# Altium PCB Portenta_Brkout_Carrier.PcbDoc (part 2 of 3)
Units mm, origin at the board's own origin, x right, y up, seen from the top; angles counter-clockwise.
Board outline 163.96 x 72.14 mm, 4 copper layers (Top, GND, PWR, Bottom), stack 1.612 mm thick; 71 components, 171 nets, 700 pads, 387 vias.
Unrouted connection lines stored in the file: 2.
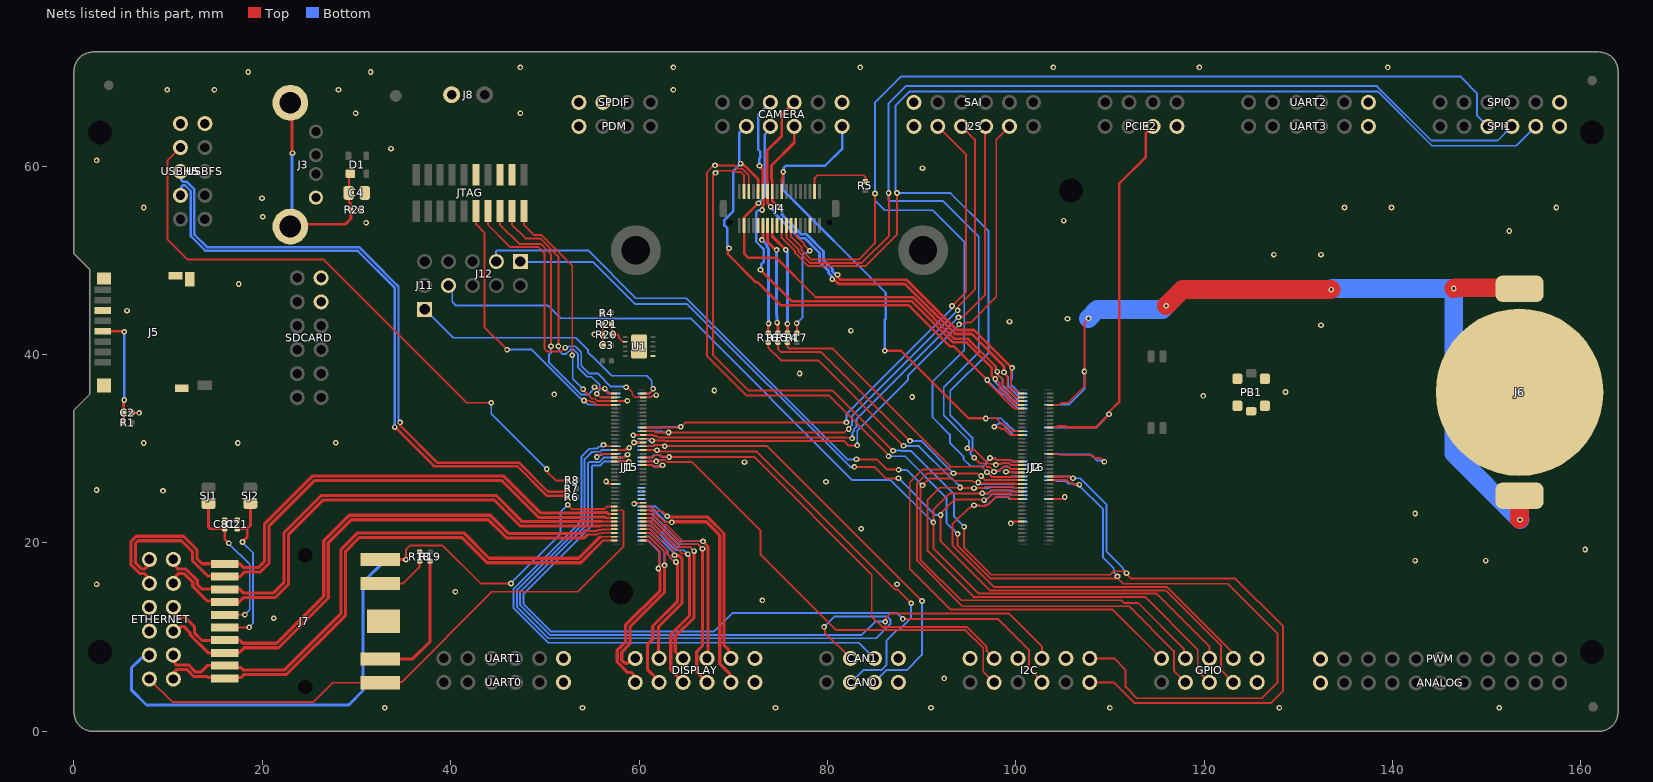
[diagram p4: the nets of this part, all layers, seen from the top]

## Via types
v1: diameter 0.6, hole 0.3, Top to Bottom, tented both sides, 387 vias

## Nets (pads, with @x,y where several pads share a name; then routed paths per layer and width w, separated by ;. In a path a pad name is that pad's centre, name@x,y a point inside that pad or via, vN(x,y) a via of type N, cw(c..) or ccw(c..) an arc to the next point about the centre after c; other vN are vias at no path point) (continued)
CAM.D1_1_P: CAMERA.10 J2.10 J4.28 J16.10 | length 62
  Top w0.2: v1(96.977,37.303) 97.053,37.227 97.053,37.051 99.695,34.41 99.754,34.41 99.9,34.264 J2.10@100.57,34.264
  Top w0.264: v1@69.537,51.287 69.473,51.222 69.473,50.997 69.44,50.964 69.44,50.652 72.423,47.669 72.627,47.669 75.032,45.264 88.607,45.264 92.976,40.895 93.385,40.895 v1(96.977,37.303) ; v1(70.79,60.274) 70.881,60.274 71.057,60.098 71.182,60.098 72.65,58.63 J4.28@72.65,57.324
  Bottom w0.2: v1(96.977,37.303) 98.532,35.748 98.71,35.748 99.824,34.634 99.879,34.634 100.244,34.269 100.825,34.269 J16.10@100.83,34.264
  Bottom w0.264: v1@69.537,51.287 69.537,51.378 69.369,51.545 69.369,53.433 69.034,53.768 69.034,54.252 70.025,55.243 70.025,59.508 70.68,60.163 v1(70.79,60.274) ; v1@70.667,60.177 70.637,60.207 70.637,63.53 71.347,64.24 CAMERA.10@71.4,64.24
  other v1: 69.551,51.293
CAM.D2_1_N: CAMERA.7 J2.8 J4.26 J16.8 | length 58.5
  Top w0.2: v1(97.819,37.407) 98.287,36.94 98.287,36.28 99.83,34.737 99.889,34.737 99.962,34.664 J2.8@100.57,34.664
  Top w0.264: v1(72.791,60.05) 72.791,59.959 73.15,59.6 J4.26@73.15,57.324 73.168,57.306 73.168,56.391 73.25,56.309 73.25,55.846 73.134,55.73 73.134,55.415 v1(73.07,55.351) ; v1(72.9,49) 76.245,45.655 88.968,45.655 93.337,41.286 94.783,41.286 97.472,38.597 97.472,37.73 97.795,37.407 v1(97.819,37.407)
  Bottom w0.2: v1(97.819,37.407) 97.896,37.331 97.896,37.024 99.959,34.961 100.014,34.961 100.306,34.669 100.825,34.669 J16.8@100.83,34.664
  Bottom w0.264: v1(72.791,60.05) 72.791,60.794 72.875,60.878 72.875,61.54 72.669,61.746 72.669,65.509 CAMERA.7@73.94,66.78 ; v1(72.9,49) 72.964,49.064 72.964,49.559 73.234,49.828 73.234,51.202 72.45,51.986 72.45,55.11 72.652,55.312 73.032,55.312 v1(73.07,55.351)
CAM.D2_1_P: CAMERA.8 J2.6 J4.33 J16.6 | length 56
  Top w0.2: v1@98.007,38.111 98.108,38.01 98.108,37.864 98.614,37.358 98.614,36.416 99.966,35.064 J2.6@100.57,35.064
  Top w0.264: v1(72.691,56.078) 71.168,54.554 71.168,53.742 J4.33@71.15,53.724 71.15,50.75 71.634,50.266 74.593,50.266 78.766,46.093 89.074,46.093 89.12,46.047 89.13,46.047 93.499,41.677 94.945,41.677 97.863,38.759 97.863,38.454 98.031,38.286 v1(98.031,38.195)
  Bottom w0.2: v1(98.031,38.195) 98.108,38.118 98.108,37.864 98.614,37.358 98.614,36.768 100.095,35.288 100.15,35.288 100.369,35.069 100.825,35.069 J16.6@100.83,35.064
  Bottom w0.264: v1(72.691,56.078) 73.35,56.737 73.35,63.37 73.94,63.96 CAMERA.8@73.94,64.24
CAM.D3_1_N: CAMERA.5 J2.4 J4.24 J16.4 | length 53.4
  Top w0.2: v1(98.755,38.125) 98.755,38.035 99.104,37.685 99.104,36.388 100.028,35.464 J2.4@100.57,35.464
  Top w0.3: v1(73.973,55.701) 73.973,55.782 73.659,56.096 73.659,56.479 73.65,56.488 J4.24@73.65,57.324 73.65,58.372 73.595,58.427 73.595,61.66 75.162,63.227 75.162,65.462 CAMERA.5@76.48,66.78 ; v1(80.525,48) 80.705,48 81.209,47.496 88.259,47.496 93.58,42.175 95.343,42.175 98.761,38.757 98.761,38.447 98.757,38.444 98.757,38.127 v1(98.755,38.125)
  Bottom w0.2: v1(98.755,38.125) 98.755,38.019 99.197,37.577 99.197,36.648 100.23,35.615 100.285,35.615 100.431,35.469 100.825,35.469 J16.4@100.83,35.464
  Bottom w0.3: v1(73.973,55.701) 73.973,55.623 74.465,55.132 74.465,54.94 77.057,52.348 77.608,52.348 79.169,50.788 79.169,49.842 80.115,48.897 80.115,48.673 80.468,48.32 80.468,48.057 v1(80.525,48)
CAM.D3_1_P: CAMERA.6 J2.2 J4.22 J16.2 | length 49.6
  Top w0.2: v1(99.619,38.59) 99.619,38.482 99.486,38.349 99.486,37.32 99.481,37.314 99.481,36.474 99.786,36.169 100.015,36.169 100.32,35.864 J2.2@100.57,35.864
  Top w0.264: J4.22@74.15,57.324 74.168,57.306 74.168,56.306 v1(74.797,55.677)
  Top w0.3: J4.22@74.15,57.324 74.15,58.548 74.073,58.625 74.073,60.094 76.48,62.501 CAMERA.6@76.48,64.24 ; v1(81.073,48.478) 81.073,48.269 81.396,47.946 88.413,47.946 93.731,42.628 95.581,42.628 v1(99.619,38.59)
  Bottom w0.2: v1(99.619,38.59) 99.619,37.422 99.524,37.327 99.524,36.783 100.365,35.942 100.457,35.942 J16.2@100.53,35.869
  Bottom w0.3: v1(74.797,55.677) 74.797,55.596 75.167,55.226 75.167,54.842 77.234,52.775 77.785,52.775 79.596,50.964 79.596,50.019 80.542,49.074 80.542,48.849 80.763,48.628 80.842,48.628 80.992,48.478 v1(81.073,48.478)
CAM.HS_1: CAMERA.2 J2.22 J4.18 J16.22 | length 58.2
  Top w0.2: v1(96.823,33.222) 96.847,33.246 97.938,33.246 98.736,32.448 98.941,32.448 99.525,31.864 J2.22@100.57,31.864
  Top w0.264: J4.18@75.15,57.324 75.15,58.541 75.241,58.632 75.241,59.355 v1@75.3,59.414 ; v1(86.099,40.411) 87.825,40.411 95.014,33.222 v1(96.823,33.222)
  Bottom w0.2: v1(96.823,33.222) 96.847,33.246 98.437,33.246 99.011,32.672 99.066,32.672 99.874,31.864 J16.22@100.83,31.864
  Bottom w0.264: CAMERA.2@81.56,64.24 81.56,61.849 79.775,60.064 75.613,60.064 75.36,59.811 75.36,59.474 75.3,59.414 75.3,57.464 86.2,46.564 86.2,43.827 86.099,43.726 v1(86.099,40.411)
  other v1: 75.314,59.421
CAN0.RX_1: CAN0.3 J1.52 J15.52 | length 51
  Top w0.2: J1.52@60.47,30.264 61.551,30.264 61.689,30.402 62.491,30.402 62.541,30.352 v1@62.687,30.352 ; v1(62.726,30.275) 73.611,30.275 v1(90.043,13.843)
  Bottom w0.19: J15.52@60.23,30.264 61.558,30.264 61.691,30.397 62.493,30.397 62.615,30.275 v1(62.726,30.275)
  Bottom w0.2: CAN0.3@85,5.2 86.328,6.528 88.465,6.528 90.043,8.106 v1(90.043,13.843)
CAN0.TX_1: CAN0.2 J1.50 J15.50 | length 49.5
  Top w0.2: J1.50@60.47,29.864 61.654,29.864 61.809,29.709 61.917,29.709 v1(61.917,29.852) ; v1@61.974,29.709 72.526,29.709 79.849,22.386 87.173,15.062 87.427,15.062 v1(88.9,13.589)
  Bottom w0.19: J15.50@59.99,29.864 61.905,29.864 v1(61.917,29.852)
  Bottom w0.2: CAN0.2@82.46,5.2 82.511,5.2 83.808,6.497 85.733,6.497 86.263,7.027 86.263,9.628 87.418,10.783 87.634,10.783 88.9,12.049 v1(88.9,13.589)
CAN1.RX_1: CAN1.3 J1.51 J15.51 | length 65.2
  Top w0.19: v1(56.222,30.409) 56.3,30.33 56.525,30.33 56.593,30.262 56.595,30.264 J1.51@57.39,30.264
  Bottom w0.19: v1(56.222,30.409) 56.3,30.33 56.59,30.33 56.657,30.264 J15.51@57.65,30.264
  Bottom w0.2: v1(56.222,30.409) 56.113,30.409 55.913,30.209 55.739,30.209 55.554,30.024 55.157,30.024 55.135,30.002 54.705,30.002 53.88,29.177 53.88,22.325 46.677,15.122 46.677,13.091 50.37,9.398 83.342,9.398 CAN1.3@85,7.74
CAN1.TX_1: CAN1.2 J1.49 J15.49 | length 79.8
  Top w0.19: J1.49@57.39,29.864 58.463,29.864 58.527,29.928 58.662,29.928 58.849,30.115 v1(58.96,30.115)
  Top w0.2: v1(79.659,11.091) 79.736,11.014 79.736,10.464 CAN1.2@82.46,7.74
  Bottom w0.19: 54.975,29.646 54.986,29.657 55.277,29.657 55.299,29.679 55.811,29.679 55.996,29.864 J15.49@57.65,29.864 58.484,29.864 58.536,29.916 58.592,29.916 58.614,29.938 58.672,29.938 58.849,30.115 v1(58.96,30.115)
  Bottom w0.2: 54.975,29.646 54.23,28.901 54.23,22.18 47.027,14.977 47.027,13.236 50.379,9.884 85.171,9.884 86.701,11.414 86.701,11.87 86.379,12.192 80.76,12.192 v1(79.659,11.091)
CIPO_OMV_1: J2.40 J4.15 J16.40 SPI1.4 | length 145.5
  Top w0.2: J4.15@75.65,53.724 75.65,52.439 76.917,51.172 76.917,50.951 78.128,49.739 83.664,49.739 86.55,52.625 86.55,57.108 v1(86.5,57.159) ; v1(94.848,30.059) 94.956,30.059 95.147,29.868 95.655,29.868 97.108,28.415 97.405,28.415 97.454,28.366 97.82,28.366 v1(97.897,28.289) 97.974,28.366 98.489,28.366 98.587,28.464 99.308,28.464 99.348,28.424 99.374,28.424 99.534,28.264 J2.40@100.57,28.264
  Bottom w0.2: v1(94.848,30.059) 94.848,30.167 95.039,30.358 95.039,30.874 92.355,33.558 92.355,36.515 96.076,40.236 96.076,52.507 92.283,56.3 86.617,56.3 86.5,56.417 v1(86.5,57.159) 86.5,66.684 88.33,68.514 138.352,68.514 144.133,62.733 151.173,62.733 SPI1.4@152.68,64.24 ; v1(97.897,28.289) 97.974,28.366 98.443,28.366 98.541,28.464 99.333,28.464 99.533,28.264 J16.40@100.83,28.264
CK_OMV_1: J2.38 J4.13 J16.38 SPI1.3 | length 145
  Top w0.2: J4.13@76.15,53.724 76.15,52.496 77.267,51.379 77.267,51.096 78.273,50.089 83.307,50.089 85.05,51.832 v1(85.05,57.108) ; v1(97.274,29.027) 97.341,28.959 97.874,28.959 98.004,28.829 98.193,28.829 98.206,28.816 99.451,28.816 99.493,28.774 99.519,28.774 99.629,28.664 J2.38@100.57,28.664
  Bottom w0.2: v1(97.274,29.027) 97.268,29.027 96.914,28.673 96.914,28.477 96.579,28.142 95.216,28.142 94.445,28.914 94.445,29.19 93.016,30.618 93.016,31.497 91.163,33.35 91.163,37.094 94.539,40.47 94.539,51.969 91.183,55.325 86.09,55.325 85.05,56.365 v1(85.05,57.108) 85.05,66.729 87.86,69.539 147.177,69.539 148.999,67.717 148.999,65.381 SPI1.3@150.14,64.24 ; v1@97.329,29.082 97.457,28.954 97.874,28.954 97.994,28.834 98.188,28.834 98.208,28.814 99.478,28.814 99.628,28.664 J16.38@100.53,28.664
COPI_OMV_1: J2.42 J4.17 J16.42 SPI1.5 | length 149.4
  Top w0.2: J4.17@75.15,53.724 75.15,52.414 76.567,50.997 76.567,50.806 77.984,49.389 84.021,49.389 87.399,52.767 v1(87.399,57.159) ; v1(95.589,29.042) 96.192,28.439 96.589,28.439 96.963,28.065 97.26,28.065 97.7,27.624 v1(97.7,27.566) ; v1@97.711,27.614 97.787,27.69 98.308,27.69 98.732,28.114 99.163,28.114 99.203,28.074 99.229,28.074 99.439,27.864 J2.42@100.57,27.864
  Bottom w0.2: v1(95.589,29.042) 95.207,29.424 95.207,29.64 95.398,29.831 95.398,31.194 93.053,33.539 93.053,36.136 97.126,40.209 97.126,53.103 93.07,57.159 v1(87.399,57.159) 87.399,57.177 87.25,57.326 87.25,66.464 88.725,67.939 138.432,67.939 144.201,62.17 153.15,62.17 SPI1.5@155.22,64.24 ; v1(97.7,27.566) 97.777,27.642 98.26,27.642 98.582,27.964 98.732,28.114 99.188,28.114 99.338,27.964 99.438,27.864 J16.42@100.53,27.864
CS_OMV_1: J4.11 R17.1 | length 12.9
  Top w0.2: J4.11@76.65,53.724 76.65,52.624 77.523,51.752 77.523,51.618 v1(78.12,51.02) ; v1@76.725,43.314 76.773,43.266 R17.1@76.773,42.264
  Bottom w0.2: v1@76.725,43.314 77.375,43.964 77.375,50.614 77.516,50.756 77.747,50.756 78.012,51.02 v1(78.12,51.02)
  other v1: 76.739,43.321
D_1_N: R7.1 USBHS.3 | length 67.2
  Top w0.264: v1(34.63,32.806) 34.654,32.782 34.654,32.441 38.554,28.541 47.238,28.541 50.358,25.42 52.089,25.42 52.4,25.732 R7.1@52.4,25.75
  Bottom w0.264: USBHS.3@11.31,59.45 11.412,59.348 11.412,58.531 11.567,58.376 11.948,58.376 12.797,57.526 12.797,52.745 12.877,52.666 14.125,51.418 30.271,51.418 31.482,50.207 31.6,50.089 34.324,47.365 34.462,47.227 34.462,33.065 34.63,32.897 v1(34.63,32.806)
D_1_P: R6.1 USBHS.2 | length 67.2
  Top w0.264: v1(34.071,32.297) 38.218,28.149 47.076,28.149 50.196,25.029 52.102,25.029 52.128,25.003 52.258,25.003 52.4,24.861 R6.1@52.4,24.85
  Bottom w0.264: USBHS.2@11.31,56.91 11.412,57.013 11.412,57.83 11.567,57.985 11.786,57.985 12.406,57.364 12.406,52.583 13.963,51.027 30.109,51.027 34.071,47.065 v1(34.071,32.297)
DISPLAY.CLK_1_N: DISPLAY.10 J1.20 J15.20 | length 26.6
  Top w0.19: J1.20@60.47,23.864 61.167,23.864 61.335,23.695 61.538,23.695 61.858,23.375 62.46,23.375 62.931,22.904 v1@62.931,22.793 ; v1@62.931,22.777 v1(62.994,22.84)
  Top w0.328: v1@62.931,22.777 67.254,22.777 69.032,21 69.032,9.133 69.517,8.648 69.517,7.983 DISPLAY.10@69.76,7.74
  Bottom w0.19: J15.20@60.23,23.864 60.234,23.867 61.774,23.867 62.723,22.919 62.916,22.919 v1(62.994,22.84)
DISPLAY.CLK_1_P: DISPLAY.9 J1.18 J15.18 | length 29.1
  Top w0.19: J1.18@60.47,23.464 61.118,23.464 61.204,23.378 61.407,23.378 61.727,23.058 61.846,23.058 62.682,22.222 63.44,22.222 v1(63.476,22.186)
  Top w0.328: v1(63.476,22.186) 63.528,22.238 63.72,22.238 63.733,22.251 67.137,22.251 68.577,20.811 68.577,7.166 69.64,6.103 69.64,5.32 DISPLAY.9@69.76,5.2
  Bottom w0.19: J15.18@60.23,23.464 61.633,23.464 62.875,22.222 63.44,22.222 v1(63.476,22.186)
DISPLAY.D0_1_N: DISPLAY.8 J1.16 J15.16 | length 28
  Top w0.19: J1.16@60.47,23.064 61.07,23.064 61.073,23.061 61.276,23.061 61.596,22.741 61.714,22.741 62.55,21.905 62.935,21.905 64.671,20.17 v1(66.789,20.17)
  Top w0.328: v1(66.789,20.17) 67.331,19.628 67.331,7.851 DISPLAY.8@67.22,7.74
  Bottom w0.19: J15.16@60.23,23.064 61.391,23.064 64.285,20.17 v1(66.789,20.17)
DISPLAY.D0_1_P: DISPLAY.7 J1.14 J15.14 | length 30.4
  Top w0.19: J1.14@60.47,22.664 61.225,22.664 61.465,22.424 61.583,22.424 62.458,21.549 62.843,21.549 64.539,19.853 66.27,19.853 v1(66.74,19.383)
  Top w0.328: v1(66.74,19.383) 66.74,9.087 66.129,8.476 66.129,6.291 DISPLAY.7@67.22,5.2
  Bottom w0.19: J15.14@60.23,22.664 61.343,22.664 64.154,19.853 66.27,19.853 v1(66.74,19.383)
DISPLAY.D1_1_N: DISPLAY.6 J1.12 J15.12 | length 26.2
  Top w0.19: J1.12@60.47,22.264 61.176,22.264 61.333,22.107 61.452,22.107 62.327,21.232 62.686,21.232 64.382,19.536 65.427,19.536 65.831,19.132 v1(65.851,19.132)
  Top w0.33: DISPLAY.6@64.68,7.74 64.574,7.74 63.848,8.466 63.848,10.08 65.851,12.083 v1(65.851,19.132)
  Bottom w0.19: J15.12@60.23,22.264 61.295,22.264 64.023,19.536 65.427,19.536 65.831,19.132 v1(65.851,19.132)
DISPLAY.D1_1_P: DISPLAY.5 J1.10 J15.10 | length 27.3
  Top w0.19: J1.10@60.47,21.864 61.105,21.864 61.179,21.79 61.32,21.79 62.195,20.915 62.555,20.915 64.606,18.864 65.142,18.864 v1(65.191,18.815)
  Top w0.33: DISPLAY.5@64.68,5.2 63.368,6.512 63.368,10.279 65.366,12.277 65.366,18.567 65.191,18.742 v1(65.191,18.815)
  Bottom w0.19: J15.10@60.23,21.864 61.246,21.864 63.892,19.219 64.768,19.219 65.171,18.815 v1(65.191,18.815)
DISPLAY.D2_1_N: DISPLAY.4 J1.8 J15.8 | length 22.1
  Top w0.19: J1.8@60.47,21.464 61.198,21.464 62.406,20.256 62.67,20.256 63.503,19.423 63.503,19.289 63.715,19.077 63.715,18.751 v1(63.776,18.69)
  Top w0.33: DISPLAY.4@62.14,7.74 62.088,7.792 62.088,11.133 64.582,13.627 64.582,18.34 64.277,18.645 63.821,18.645 v1(63.776,18.69)
  Bottom w0.19: J15.8@60.23,21.464 61.198,21.464 63.698,18.965 63.698,18.769 v1(63.776,18.69)
DISPLAY.D2_1_P: DISPLAY.3 J1.6 J15.6 | length 25
  Top w0.19: J1.6@60.47,21.064 61.15,21.064 63.022,19.192 63.022,18.822 63.254,18.589 63.254,18.474 63.56,18.168 63.634,18.168 63.822,17.98 v1(63.933,17.98)
  Top w0.33: DISPLAY.3@62.14,5.2 62.14,5.342 60.882,6.6 60.882,9.192 61.459,9.769 61.459,11.183 64.102,13.826 64.102,17.737 63.933,17.907 v1(63.933,17.98)
  Bottom w0.19: J15.6@60.23,21.064 61.15,21.064 63.022,19.192 63.022,18.822 63.254,18.589 63.254,18.474 63.56,18.168 63.634,18.168 63.822,17.98 v1(63.933,17.98)
DISPLAY.D3_1_N: DISPLAY.2 J1.4 J15.4 | length 22.7
  Top w0.19: J1.4@60.47,20.664 61.102,20.664 62.705,19.061 v1(62.705,17.622)
  Top w0.33: DISPLAY.2@59.6,7.74 59.289,7.74 58.772,7.222 58.498,7.222 58.167,7.554 58.167,8.406 59.035,9.274 59.035,11.081 62.705,14.751 v1(62.705,17.622)
  Bottom w0.19: J15.4@60.23,20.664 60.561,20.664 60.567,20.67 61.095,20.67 62.705,19.061 v1(62.705,17.622)
DISPLAY.D3_1_P: DISPLAY.1 J1.2 J15.2 | length 23.4
  Top w0.19: J1.2@60.47,20.264 61.053,20.264 62.183,19.135 62.183,17.607 62.136,17.561 62.136,17.369 v1(62.057,17.291)
  Top w0.33: DISPLAY.1@59.6,5.2 59.407,5.393 59.407,6.037 59.213,6.23 58.812,6.23 57.687,7.355 57.687,8.605 58.555,9.473 58.555,11.247 62.248,14.94 62.248,17.028 62.057,17.218 v1(62.057,17.291)
  Bottom w0.19: J15.2@60.23,20.264 60.915,20.264 62.183,18.996 62.183,17.607 62.136,17.561 62.136,17.369 v1(62.057,17.291)
ETH.A_1_N: ETHERNET.3 J1.3 J7.P2 | length 60.6
  Top w0.2: 55.885,20.644 55.904,20.664 J1.3@57.39,20.664
  Top w0.328: ETHERNET.3@10.55,8.09 10.67,7.97 10.67,7.251 10.862,7.059 12.17,7.059 12.951,6.278 13.453,6.278 14.15,6.975 J7.P2@16.005,6.975 16.208,6.772 17.717,6.772 17.961,6.528 22.368,6.528 28.367,12.527 28.367,19.317 30.126,21.076 41.379,21.076 44.077,18.378 53.619,18.378 55.885,20.644
ETH.A_1_P: ETHERNET.1 J1.1 J7.P1 | length 60.3
  Top w0.2: 56.136,20.211 56.188,20.264 J1.1@57.39,20.264
  Top w0.328: ETHERNET.1@10.55,5.55 10.741,5.741 10.741,6.389 10.933,6.581 11.972,6.581 12.753,5.8 13.863,5.8 13.875,5.813 14.147,5.813 14.255,5.705 15.925,5.705 J7.P1@16.005,5.625 16.1,5.72 17.755,5.72 18.085,6.05 22.566,6.05 28.845,12.329 28.845,19.119 30.324,20.598 41.181,20.598 43.879,17.9 53.817,17.9 56.128,20.211 56.136,20.211
ETH.B_1_N: ETHERNET.7 J1.7 J7.P4 | length 59.2
  Top w0.2: 54.392,21.325 54.618,21.325 54.691,21.252 55.445,21.252 55.578,21.385 55.963,21.385 56.017,21.439 56.974,21.439 56.999,21.464 J1.7@57.39,21.464
  Top w0.328: ETHERNET.7@10.55,13.17 10.793,12.927 10.793,12.42 11.074,12.139 11.776,12.139 12.784,11.131 12.784,10.469 13.603,9.65 15.98,9.65 J7.P4@16.005,9.675 16.019,9.689 17.6,9.689 17.936,9.353 21.528,9.353 26.522,14.347 26.522,20.223 29.241,22.941 44.202,22.941 46.123,21.02 53.998,21.02
  Top w0.33: 53.998,21.02 54.303,21.325 54.392,21.325
ETH.B_1_P: ETHERNET.5 J1.5 J7.P3 | length 58.7
  Top w0.2: 54.507,20.85 54.559,20.902 55.59,20.902 55.723,21.035 56.108,21.035 56.162,21.089 56.974,21.089 56.999,21.064 J1.5@57.39,21.064
  Top w0.328: ETHERNET.5@10.55,10.63 10.863,10.63 11.378,11.145 11.65,11.145 12.306,10.489 12.306,10.271 14.252,8.325 J7.P3@16.005,8.325 16.069,8.389 17.6,8.389 18.086,8.875 21.726,8.875 27,14.149 27,20.025 29.439,22.463 44.004,22.463 45.338,21.129 45.925,20.542 54.197,20.542
  Top w0.33: 54.198,20.542 54.506,20.85
ETH.C_1_N: ETHERNET.11 J1.11 J7.P8 | length 57.4
  Top w0.2: 56.088,22.296 56.12,22.264 J1.11@57.39,22.264
  Top w0.328: ETHERNET.11@10.55,18.25 10.793,18.007 10.793,17.5 11.074,17.219 11.906,17.219 13.089,16.036 13.089,15.59 13.59,15.089 16.005,15.089 17.388,15.089 17.6,15.089 17.986,14.703 21.208,14.703 22.287,15.782 22.287,21.057 26.286,25.056 44.809,25.056 47.606,22.259 54.765,22.259 54.802,22.296 56.088,22.296
ETH.C_1_P: ETHERNET.9 J1.9 J7.P7 | length 57.9
  Top w0.2: 55.843,21.818 55.889,21.864 J1.9@57.39,21.864
  Top w0.328: ETHERNET.9@10.55,15.71 10.793,15.953 10.793,16.46 11.074,16.741 11.708,16.741 12.611,15.838 12.611,15.392 13.842,14.161 14.166,13.838 15.892,13.838 J7.P7@16.005,13.725 16.041,13.689 17.5,13.689 18.036,14.225 21.406,14.225 22.765,15.584 22.765,20.859 26.484,24.578 44.611,24.578 47.408,21.781 54.963,21.781 55,21.818 55.843,21.818
ETH.D_1_N: ETHERNET.10 J1.15 J7.P10 | length 67.1
  Top w0.2: 56.791,23.064 J1.15@57.39,23.064
  Top w0.328: ETHERNET.10@8.01,15.71 7.767,15.953 7.767,16.46 7.486,16.741 7.016,16.741 6.044,17.713 6.044,20.138 6.621,20.715 11.61,20.715 11.75,20.575 13.064,19.261 13.064,18.315 13.59,17.789 16.005,17.789 17.6,17.789 17.986,17.403 19.608,17.403 20.214,18.009 20.214,21.977 25.361,27.124 45.598,27.124 49.53,23.192 53.98,23.192 54.017,23.229 56.626,23.229 56.791,23.064
ETH.D_1_P: ETHERNET.12 J1.13 J7.P9 | length 66
  Top w0.2: 56.465,22.712 56.513,22.664 56.604,22.664 56.618,22.65 56.962,22.65 56.976,22.664 J1.13@57.39,22.664
  Top w0.328: ETHERNET.12@7.945,18.25 ETHERNET.12@8.01,18.25 7.767,18.007 7.767,17.5 7.486,17.219 7.214,17.219 6.522,17.911 6.522,19.94 6.819,20.237 11.412,20.237 12.586,19.063 12.586,18.117 14.228,16.475 15.955,16.475 J7.P9@16.005,16.425 16.041,16.389 17.6,16.389 18.136,16.925 19.806,16.925 20.692,17.811 20.692,21.779 25.559,26.646 45.4,26.646 49.332,22.714 54.219,22.714 54.256,22.751 56.426,22.751 56.465,22.712
ETH.LED1_1: ETHERNET.2 J1.17 J7.L1 | length 62.9
  Top w0.19: J1.17@57.39,23.464 58.247,23.464 58.358,23.353 58.358,19.667
  Top w0.2: ETHERNET.2@8.01,5.55 10.433,3.127 25.468,3.127 27.491,5.15 J7.L1@32.505,5.15 32.58,5.225 34.788,5.225 44.383,14.82 53.511,14.82 58.358,19.667
ETH.LED2_1: ETHERNET.4 J1.19 J7.L4 | length 80.7
  Top w0.2: v1(35.261,18.226) 35.261,19.31 35.66,19.709 39.157,19.709 43.168,15.698 v1(46.403,15.698) ; v1(52.425,24.055) 52.897,23.583 53.653,23.583 53.69,23.62 56.367,23.62 56.611,23.864 J1.19@57.39,23.864
  Top w0.3: J7.L4@32.505,18.25 32.529,18.226 v1(35.261,18.226)
  Bottom w0.2: v1(46.403,15.698) 51.675,20.97 51.675,23.305 v1(52.425,24.055)
  Bottom w0.328: ETHERNET.4@8.01,8.09 7.747,8.09 7.43,7.773 7.148,7.773 6.1,6.725 6.1,4.4 7.7,2.8 29.175,2.8 30.7,4.325 30.7,15.825 33.101,18.226 v1(35.261,18.226)
GND: ANALOG.11 C2.1 C3.2 C4.1 C21.2 C81.2 CAMERA.1 CAN0.4 CAN1.4 DISPLAY.11 DISPLAY.12 ETHERNET.6 ETHERNET.8 GPIO.9 GPIO.10 I2C.2 I2C.6 I2C.10 I2S.6 J1.22 J1.31 J1.42 J1.47 J1.54 J2.24 J2.33 J2.44 J2.57 J2.70 J3.4 J4.5 J4.19 J4.27 J5.6 J5.CD2 J5.SH1 J5.SH2 J5.SH3 J5.SH4 J6.3 J7.S3 J8.2 J15.22 J15.31 J15.42 J15.47 J15.54 J16.24 J16.33 J16.44 J16.57 J16.70 JTAG.3 JTAG.5 JTAG.9 pad.15@105.855,57.404 PB1.5 PB1.PAD PCIE2.4 PDM.4 PWM.11 R4.2 R18.2 R20.2 R21.2 R23.1 SAI.6 SDCARD.11 SPDIF.3 SPDIF.4 SPI0.6 SPI1.6 U1.1 U1.11 UART0.6 UART1.6 UART2.6 UART3.6 USBFS.5 USBHS.5 | length 45.5
  Top w0.19: v1(59.474,30.661) 59.477,30.664 J1.54@60.47,30.664 ; v1@59.686,24.264 J1.22@60.47,24.264 ; J2.57@103.65,24.664 104.886,24.664 105.102,24.879 v1(105.213,24.879) ; J2.33@103.65,29.464 104,29.464 104.055,29.409 105.026,29.409 105.076,29.359 108.068,29.359 108.401,29.026 108.999,29.026 109.411,28.614 v1(109.415,28.614)
  Top w0.2: C2.1@6.128,33.806 6.919,33.806 v1@6.925,33.8 ; C81.2@16.005,22.406 C21.2@17.335,22.406 ; v1(55.24,42.144) 55.259,42.125 R20.2@56.119,42.125 ; v1(55.525,29.134) 55.633,29.134 55.963,29.464 J1.47@57.39,29.464 ; R21.2@56.119,43.248 R20.2@56.119,42.125 ; C3.2@56.159,41.002 56.159,42.085 R20.2@56.119,42.125 ; v1(56.51,26.518) 56.557,26.518 56.811,26.264 J1.31@57.39,26.264 ; J1.42@60.47,28.264 61.41,28.264 61.559,28.115 62.25,28.115 62.393,28.259 v1(62.502,28.259) ; v1(97.713,32.337) 97.79,32.26 98.298,32.26 98.46,32.098 98.796,32.098 99.43,31.464 J2.24@100.57,31.464 ; v1(98.96,27.564) 99.01,27.514 99.838,27.514 99.888,27.464 J2.44@100.57,27.464 ; v1(99.464,22.081) 99.573,22.081 99.756,22.264 J2.70@100.57,22.264
  Bottom w0.19: v1(59.474,30.661) 59.477,30.664 J15.54@60.23,30.664 ; v1(59.481,24.17) 59.592,24.17 59.686,24.264 J15.22@60.23,24.264 ; J16.33@103.41,29.464 104.089,29.464 104.105,29.449 104.549,29.449 104.594,29.404 107.932,29.404 108.584,28.752 109.167,28.752 109.304,28.614 v1(109.415,28.614)
  Bottom w0.2: v1(55.525,29.134) 55.633,29.134 55.833,29.334 56.008,29.334 56.138,29.464 J15.47@57.65,29.464 ; v1(56.51,26.518) 56.514,26.518 56.768,26.264 J15.31@57.65,26.264 ; J15.42@60.23,28.264 61.404,28.264 61.567,28.101 62.236,28.101 62.393,28.259 v1(62.502,28.259) ; v1(97.713,32.337) 97.821,32.337 98.18,32.696 98.492,32.696 99.724,31.464 J16.24@100.83,31.464 ; v1(98.96,27.564) 99.01,27.514 99.673,27.514 99.723,27.464 J16.44@100.83,27.464
  other v1: 33,2.5 54,2.5 74.5,2.5 91,2.5 110,2.5 128,2.5 151.339,2.5 92.408,5.62 21.208,12 73.1,13.9 40.5,14.82 2.408,15.62 87.4,15.612 142.408,18.12 149.908,18.12 160.457,19.304 83.6,21.5 142.408,23.12 9.461,25.527 2.408,25.62 79.849,26.5 71.2,28.582 7.408,30.62 17.408,30.62 27.808,30.64 6.919,33.814 89,35.5 119.908,35.62 51,35.778 128.654,36.031 68,36.193 77.053,38 82.5,42.544 132.408,43.12 99.34,43.5 105.5,43.809 5.628,44.672 17.5,47.5 127.408,50.62 132.408,50.62 152.408,53.12 31.025,54 105.093,54.229 20.04,54.645 7.408,55.62 134.908,55.62 139.908,55.62 157.408,55.62 19.965,56.595 90.1,59.8 2.408,60.62 33.665,61.87 29.908,65.62 47.408,65.62 9.908,68.12 14.908,68.12 28.097,68.12 63.648,68.12 18.5,70 31.5,70 47.408,70.5 63.648,70.5 83.5,70.5 104,70.5 119.5,70.5 139.5,70.5
GPIO.0_1: GPIO.2 J2.46 J16.46 R14.2 | length 79.8
  Top w0.2: R14.2@75.757,41.314 75.757,40.831 75.949,40.639 80.549,40.639 93.099,28.089 ; v1@96.895,27.594 97.474,27.014 99.487,27.014 99.537,27.064 J2.46@100.57,27.064 ; v1(96.952,27.515) 96.952,27.536 96.399,28.089 93.099,28.089 ; GPIO.2@115.48,7.74 110.296,12.924 93.081,12.924 88.75,17.255 88.75,26.418 90.146,27.814 92.824,27.814 93.099,28.089
  Bottom w0.2: v1(96.952,27.515) 96.973,27.515 97.474,27.014 99.487,27.014 99.537,27.064 J16.46@100.53,27.064
GPIO.1_1: GPIO.3 J2.48 J16.48 R15.2 | length 84.7
  Top w0.2: R15.2@74.741,41.314 74.741,40.598 75.05,40.289 79.316,40.289 v1(88.77,30.835) ; J2.48@100.57,26.664 99.977,26.664 96.764,26.664 96.428,27 96.428,27.103 96.217,27.103 95.926,27.394 v1(93.389,27.394) 90.602,27.394 89.525,26.317 89.525,18.089 94.34,13.274 112.043,13.274 116.794,8.523 116.794,6.426 GPIO.3@118.02,5.2
  Bottom w0.2: v1(88.77,30.835) 89.948,30.835 v1(93.389,27.394) ; v1(96.325,27.103) 96.764,26.664 J16.48@100.83,26.664
GPIO.2_1: GPIO.4 J2.50 J12.3 J16.50 | length 113.7
  Top w0.2: v1(83.099,28.881) 85.242,28.881 86.342,27.781 v1(87.564,27.781) ; J2.50@100.57,26.264 99.882,26.264 99.832,26.314 96.59,26.314 96.561,26.343 96.092,26.343 95.939,26.497 95.418,26.497 95.315,26.599 93.527,26.599 93.288,26.839 90.825,26.839 v1(90.1,26.114) 89.875,25.889 89.875,18.234 94.195,13.914 111.218,13.914 111.508,13.624 112.986,13.624 117.887,8.723 117.887,7.873 GPIO.4@118.02,7.74
  Bottom w0.2: J12.3@44.813,49.818 44.813,50.951 44.93,51.068 54.596,51.068 59.677,45.987 65.011,45.987 82.124,28.874 82.29,28.874 82.296,28.881 v1(83.099,28.881) ; v1(87.564,27.781) 87.611,27.734 88.48,27.734 v1(90.1,26.114) ; v1(96.015,26.42) 96.124,26.42 96.281,26.263 98.055,26.263 98.056,26.264 99.672,26.264 ; J16.50@100.83,26.264 100.829,26.263 99.673,26.263 ; 99.672,26.264 99.673,26.263
GPIO.3_1: GPIO.5 J2.52 J16.52 R16.2 | length 85.4
  Top w0.2: R16.2@73.725,41.314 73.725,40.739 75.08,39.384 79.025,39.384 v1(88.08,30.329) ; v1(94.093,25.887) 94.07,25.864 91.934,25.864 90.65,24.58 90.65,19.15 95.536,14.264 113.73,14.264 119.33,8.664 119.33,6.43 GPIO.5@120.56,5.2 ; v1@94.189,25.864 94.199,25.854 95.532,25.854 v1(95.565,25.82) ; v1@95.594,25.791 95.623,25.82 96.598,25.82 96.742,25.964 99.687,25.964 99.787,25.864 J2.52@100.57,25.864
  Bottom w0.2: v1(88.08,30.329) 88.124,30.285 89.72,30.285 93.161,26.844 93.232,26.844 94.093,25.983 v1(94.093,25.887) ; v1(95.565,25.82) 97.12,25.82 97.213,25.913 98.2,25.913 98.201,25.914 99.527,25.914 99.528,25.913 99.713,25.913 99.762,25.864 J16.52@100.83,25.864
GPIO.4_1: GPIO.6 J2.54 J12.8 J16.54 | length 116.3
  Top w0.2: v1(96.438,25.27) 93.006,25.27 91.259,23.523 v1(91.259,22.181) 91.259,19.441 96.086,14.614 114.986,14.614 120.56,9.04 GPIO.6@120.56,7.74 ; v1@96.477,25.309 96.516,25.27 97.124,25.27 97.468,25.614 99.542,25.614 99.692,25.464 J2.54@100.57,25.464
  Bottom w0.2: J12.8@40.164,47.341 40.164,45.601 40.534,45.231 50.293,45.231 51.667,43.857 55.724,43.857 55.742,43.839 65.508,43.839 82.666,26.681 86.713,26.681 91.163,22.231 91.182,22.231 91.232,22.181 v1(91.259,22.181) ; v1(96.438,25.27) 97.065,25.27 97.358,25.563 98.345,25.563 98.346,25.564 99.46,25.564 99.56,25.464 J16.54@100.83,25.464
GPIO.5_1: GPIO.7 J2.56 J12.1 J16.56 | length 111.6
  Top w0.2: v1(82.864,28.081) 84.978,28.081 86.196,26.863 v1(87.555,26.863) ; v1@96.581,24.593 96.553,24.621 93.532,24.621 92.044,23.133 92.044,22.983 v1(92.025,22.964) 92.025,20.169 97.23,14.964 115.936,14.964 121.806,9.094 121.806,6.494 GPIO.7@123.1,5.2 ; v1(96.646,24.55) 96.723,24.626 96.975,24.626 97.613,25.264 99.397,25.264 99.597,25.064 J2.56@100.57,25.064
  Bottom w0.2: J12.1@47.324,49.851 55.102,49.851 59.588,45.365 65.125,45.365 82.409,28.081 v1(82.864,28.081) ; v1(87.555,26.863) 91.454,22.964 v1(92.025,22.964) ; v1(96.646,24.55) 96.723,24.626 96.916,24.626 97.503,25.213 98.49,25.213 98.491,25.214 99.315,25.214 99.465,25.064 J16.56@100.83,25.064
GPIO.6_1: GPIO.8 J2.58 J16.58 | length 51.8
  Top w0.2: J2.58@100.57,24.664 99.502,24.664 99.252,24.914 97.925,24.914 97.023,24.012 96.762,24.012 96.659,23.909 96.213,23.909 96.165,23.957 95.618,23.957 v1(95.565,24.01) 95.457,24.01 95.135,23.688 95.004,23.688 93.28,21.964 93.28,19.733 97.699,15.314 116.081,15.314 122.832,8.563 122.832,8.008 GPIO.8@123.1,7.74
  Bottom w0.2: v1(95.565,24.01) 95.618,23.957 96.165,23.957 96.213,23.909 96.669,23.909 96.76,24 96.874,24 96.983,24.109 97.107,24.109 97.854,24.856 98.628,24.856 98.636,24.864 99.17,24.864 99.37,24.664 J16.58@100.83,24.664
I2C0.SCL_1: I2C.4 J1.46 J15.46 | length 52.4
  Top w0.19: J1.46@60.47,29.064 61.455,29.064 61.698,29.307 62.142,29.307 62.285,29.164
  Top w0.2: 62.285,29.164 63.169,29.164 v1(63.201,29.132) 72.214,29.132 84.709,16.637 84.709,12.182 84.826,12.065 84.836,12.065 85.809,11.092 94.808,11.092 96.904,8.996 96.904,8.536 I2C.4@97.7,7.74
  Bottom w0.19: J15.46@60.23,29.064 61.337,29.064 61.577,29.304 62.284,29.304 62.456,29.132 v1(63.201,29.132) v1@63.133,29.064
I2C0.SDA_1: I2C.3 J1.44 J15.44 | length 51.6
  Top w0.19: J1.44@60.47,28.664 v1(61.826,28.665) v1(61.826,28.665)
  Top w0.2: v1(61.826,28.665) 61.903,28.742 62.206,28.742 62.274,28.809 62.746,28.809 62.973,28.582 65.652,28.582 72.898,21.336 72.898,18.796 80.952,10.742 94.663,10.742 96.554,8.851 96.554,6.346 I2C.3@97.7,5.2
  Bottom w0.19: J15.44@60.23,28.664 60.561,28.664 v1(61.826,28.665) v1(61.826,28.665)
I2C1.SCL_1: I2C.8 J1.45 J15.45 | length 84.7
  Top w0.19: J1.45@57.39,29.064 58.377,29.064 58.696,29.383 v1(58.774,29.383)
  Top w0.2: v1(86.151,11.642) 86.227,11.719 86.227,12.075 86.651,12.499 99.295,12.499 102.78,9.014 I2C.8@102.78,7.74
  Bottom w0.19: J15.45@57.65,29.064 58.377,29.064 58.696,29.383 v1(58.774,29.383)
  Bottom w0.2: J15.45@57.65,29.064 56.233,29.064 55.753,28.584 54.697,28.584 54.58,28.467 54.58,22.035 47.377,14.832 47.377,13.381 50.524,10.234 83.653,10.234 85.061,11.642 v1(86.151,11.642)
I2C1.SDA_1: I2C.7 J1.43 J15.43 | length 84.7
  Top w0.2: J1.43@57.39,28.664 57.699,28.664 58.885,28.664 v1(58.925,28.623) ; v1(88.011,11.938) 98.095,11.938 101.424,8.609 101.424,6.739 102.78,5.383 I2C.7@102.78,5.2
  Bottom w0.2: v1(58.925,28.623) 58.885,28.664 J15.43@57.65,28.664 56.328,28.664 55.898,28.234 55.112,28.234 54.995,28.117 54.995,21.82 47.727,14.552 47.727,13.526 50.669,10.584 67.946,10.584 69.904,12.542 87.407,12.542 v1(88.011,11.938)
I2C2.SCL_1: I2C.12 J2.47 J4.32 J16.47 | length 148.5
  Top w0.2: v1@67.955,60.089 67.2,59.334 67.2,39.877 71.438,35.639 80.175,35.639 86.507,29.307 v1(86.507,29.206) ; v1@68.05,60.089 70.1,60.089 70.317,59.872 70.432,59.872 70.565,59.739 70.957,59.739 71.65,59.046 J4.32@71.65,57.324 ; v1(93.83,20.964) 93.83,19.678 97.279,16.229 110.782,16.229 v1@110.807,16.254 ; J2.47@103.65,26.664 105.455,26.664 105.832,26.287 106.062,26.287 106.153,26.196 v1(106.762,26.196) ; I2C.12@107.86,7.74 110.441,7.74 111.675,6.506 111.675,4.714 112.875,3.514 126.1,3.514 127.8,5.214 127.8,10.38 122.516,15.664 111.406,15.664 110.807,16.263 v1(110.807,16.448)
  Bottom w0.2: v1(86.507,29.206) 88.244,29.206 92.63,24.82 92.63,22.164 v1(93.83,20.964) ; J16.47@103.41,26.664 104.209,26.664 104.309,26.564 105.288,26.564 105.535,26.317 106.062,26.317 106.162,26.217 106.741,26.217 v1(106.762,26.196) ; v1@106.712,26.146 109.27,23.588 109.27,18.445 110.404,17.311 110.404,16.894 110.807,16.491 v1(110.807,16.448)
  other v1: 68.064,60.096
I2C2.SDA_1: I2C.11 J2.45 J4.34 J16.45 | length 147
  Top w0.2: J4.34@71.15,57.324 71.15,59.051 70.812,59.389 70.305,59.389 70.172,59.522 68.417,59.522 68.184,59.289 68.1,59.289 67.85,59.039 67.85,39.989 71.661,36.178 80.555,36.178 86.934,29.799 v1(86.966,29.799) ; v1(94.518,21.723) 94.518,19.484 97.378,16.624 110.048,16.624 110.422,16.998 111.461,16.998 111.661,16.798 v1(111.769,16.798) ; J2.45@103.65,27.064 105.792,27.064 105.989,26.867 v1(106.086,26.867) ; I2C.11@107.86,5.2 110.389,5.2 112.575,3.014 127.114,3.014 128.4,4.3 128.4,11.145 123.331,16.214 112.253,16.214 v1@111.719,16.748
  Bottom w0.2: v1(86.966,29.799) 87.832,29.799 87.852,29.779 88.871,29.779 93.43,25.22 93.43,22.811 v1(94.518,21.723) ; J16.45@103.41,27.064 105.724,27.064 105.845,26.943 106.01,26.943 v1(106.086,26.867) ; v1@106.097,26.868 106.868,26.868 109.626,24.11 109.626,19.128 111.368,17.386 111.368,17.245 111.769,16.844 v1(111.769,16.798)
  other v1: 68.114,59.296
I2S.CK_1: I2S.2 J1.56 J15.56 | length 65.2
  Top w0.2: J1.56@60.47,31.064 61.256,31.064 61.421,30.899 v1@61.421,30.863 ; v1(61.389,30.863) 62.734,30.863 62.768,30.829 81.727,30.829 82.196,30.36 v1(83.176,30.36) ; v1(93.989,43.205) 94.062,43.278 94.589,43.278 94.71,43.399 95.206,43.399 97.929,46.122 97.929,62.829 I2S.2@99.34,64.24
  Bottom w0.19: J15.56@60.49,31.064 60.871,31.064 61.043,30.892 61.36,30.892 v1(61.389,30.863)
  Bottom w0.2: v1(83.176,30.36) 83.176,31.911 88.555,37.29 88.555,37.752 93.989,43.186 v1(93.989,43.205)
I2S.SDI_1: I2S.4 J1.60 J15.60 | length 63.1
  Top w0.19: J1.60@60.47,31.864 61.614,31.864
  Top w0.2: 61.614,31.864 61.753,31.725 63.137,31.725 v1(63.141,31.729) 81.804,31.729 82.169,32.094 v1(82.277,32.094) ; v1(93.827,44.696) 93.901,44.77 93.901,45.125 95.67,46.894 95.67,62.83 I2S.4@94.26,64.24
  Bottom w0.19: J15.60@60.402,31.864 62.423,31.864 62.556,31.731 63.139,31.731 v1(63.141,31.729)
  Bottom w0.2: v1(82.277,32.094) 82.277,32.203 82.617,32.542 82.617,33.485 v1@93.827,44.695
I2S.SDO_1: I2S.5 J1.62 J15.62 | length 63.7
  Top w0.2: J1.62@60.47,32.264 62.481,32.264 62.496,32.279 64.423,32.279 64.438,32.264 64.438,32.271 64.969,32.802 v1(82.029,32.802) ; I2S.5@91.72,64.24 94.71,61.25 94.71,46.632 v1(93.239,45.161)
  Bottom w0.19: J15.62@60.45,32.264 62.389,32.264 62.456,32.331 v1(64.438,32.331)
  Bottom w0.2: v1(82.029,32.802) 82.029,33.688 86.236,37.895 93.162,44.821 93.162,45.085 v1(93.239,45.161)
I2S.WS_1: I2S.3 J1.58 J15.58 | length 63.5
  Top w0.19: v1(59.394,31.44) 59.418,31.464 J1.58@60.47,31.464 61.526,31.464 61.631,31.359 61.856,31.359 62.002,31.213 62.04,31.213
  Top w0.2: 62.04,31.213 62.879,31.213 62.913,31.179 81.872,31.179 81.876,31.175 82.556,31.175 v1(82.626,31.105) ; v1(93.921,43.952) 93.997,44.028 94.428,44.028 96.757,46.357 96.757,64.197 I2S.3@96.8,64.24
  Bottom w0.19: v1(59.394,31.44) 59.418,31.464 J15.58@60.23,31.464
  Bottom w0.2: v1(82.626,31.105) 82.666,31.145 82.666,31.705 82.826,31.865 82.826,32.056 83.091,32.321 83.091,33.122 v1(93.921,43.952)
JTAG.R\E\S\E\T\_1: J1.73 J15.73 JTAG.10 | length 33.9
  Top w0.19: J1.73@57.39,34.664 J1.73@57.65,34.664
  Top w0.2: JTAG.10@42.694,55.24 42.694,53.826 43.59,52.93 43.59,42.924 v1(45.993,40.521) ; v1(54.156,35.126) 54.188,35.094 54.756,35.094 54.884,34.967 55.177,34.967 55.377,34.766 55.386,34.766 55.489,34.664 J1.73@57.39,34.664
  Bottom w0.19: v1(54.156,35.126) 54.618,34.664 J15.73@57.65,34.664
  Bottom w0.2: v1(45.993,40.521) 48.598,40.521 53.691,35.428 53.746,35.428 54.048,35.126 v1(54.156,35.126)
JTAG.TCK/SCK_1: J1.77 J15.77 JTAG.4 | length 30.3
  Top w0.2: JTAG.4@46.504,55.24 46.504,53.79 47.964,52.33 49.508,52.33 51.435,50.403 v1(51.435,40.883) ; v1(55.506,35.835) 55.518,35.835 55.89,35.463 57.081,35.463 57.082,35.464 J1.77@57.39,35.464
  Bottom w0.19: v1(55.506,35.835) 55.506,35.814 55.856,35.464 J15.77@57.65,35.464
  Bottom w0.2: v1(51.435,40.883) 51.512,40.806 51.512,40.385 51.823,40.073 52.279,40.073 52.737,40.531 53.075,40.531 53.514,40.092 53.514,38.648 54.516,37.646 54.955,37.646 55.825,36.777 55.825,36.263 55.506,35.943 v1(55.506,35.835)
JTAG.TDI_1: J1.78 J15.78 JTAG.8 | length 36.4
  Top w0.19: v1(58.636,36.534) 58.747,36.534 59.094,36.187 59.122,36.187 59.278,36.031 59.278,35.758 59.573,35.464 J1.78@60.47,35.464 61.25,35.464 61.409,35.623 61.757,35.623 v1(61.835,35.701)
  Top w0.2: JTAG.8@43.964,55.24 43.964,53.79 46.342,51.412 49.328,51.412 49.445,51.295 49.955,50.785 49.955,40.598 50.22,40.333 51.735,40.333 52.146,40.744 v1(52.172,40.744)
  Bottom w0.19: v1(58.636,36.534) 58.636,36.517 v1@58.781,36.372 ; J15.78@60.23,35.464 61.25,35.464 61.409,35.623 61.757,35.623 v1(61.835,35.701)
  Bottom w0.2: v1(52.172,40.744) 52.249,40.821 52.532,40.821 52.592,40.881 53.22,40.881 53.864,40.237 53.864,38.793 54.661,37.996 55.613,37.996 57,36.609 58.561,36.609 v1(58.636,36.534)
JTAG.TDO/SWO_1: J1.79 J15.79 JTAG.6 | length 30.4
  Top w0.2: JTAG.6@45.234,55.24 45.234,53.79 47.262,51.762 49.581,51.762 50.652,50.691 v1(50.652,40.883) ; v1(55.275,36.549) 55.383,36.549 55.542,36.39 v1(56.375,36.39) 56.452,36.313 56.452,36.153 56.74,35.864 J1.79@57.39,35.864
  Bottom w0.2: v1(50.652,40.883) 50.652,40.185 50.434,39.967 50.434,39.18 53.836,35.778 54.647,35.778 54.916,36.046 54.916,36.081 55.275,36.441 v1(55.275,36.549) ; v1(56.375,36.39) 56.901,35.864 J15.79@57.65,35.864
JTAG.TMS/SWD_1: J1.75 J15.75 JTAG.2 | length 28.4
  Top w0.19: J1.75@57.39,35.064 v1@58.766,35.064
  Top w0.2: JTAG.2@47.774,55.24 47.774,53.79 48.884,52.68 49.653,52.68 52.914,49.419 52.914,39.931 v1(52.906,39.922) ; v1(54.064,36.328) 54.064,36.281 55.029,35.317 55.322,35.317 55.353,35.285 55.363,35.285 55.584,35.064 J1.75@57.39,35.064
  Bottom w0.19: J15.75@57.65,35.064 58.766,35.064 v1@58.781,35.049
  Bottom w0.2: v1(52.906,39.922) 52.964,39.864 52.964,37.428 v1(54.064,36.328)
  other v1: 58.764,35.105
JTAG.TRST_1: J1.80 J11.1 J15.80 | length 31.2
  Top w0.19: J1.80@60.47,35.864 61.129,35.864 61.129,35.914 61.499,36.284 v1(61.499,36.372)
  Bottom w0.19: J15.80@60.23,35.864 61.129,35.864 61.129,35.914 61.499,36.284 v1(61.499,36.372)
  Bottom w0.2: J11.1@37.234,44.801 40.252,41.783 53.308,41.783 54.564,40.526 54.564,40.266 55.003,39.827 55.048,39.827 57.126,37.748 60.827,37.748 61.354,37.221 61.354,36.618 61.499,36.472 v1(61.499,36.372)
LICELL_1: J2.7 J6.1 J6.2 J16.7 | length 95.5
  Top w0.19: J2.7@103.65,34.664 104.635,34.664 104.834,34.863 105.542,34.863 107.291,36.612 v1(107.291,38.197) 107.291,43.406 v1(107.733,43.849)
  Top w1: v1@133.463,46.9 v1(133.5,46.9) ; J6.2@153.5,25.015 J6.2@153.502,25.014 ; v1@153.502,22.508 v1(153.54,22.47)
  Top w2: v1(115.988,45.188) 117.7,46.9 v1@133.463,46.9 ; v1(146.515,47.02) 146.6,47.106 153.38,47.106 J6.1@153.5,46.985 ; v1@153.502,22.508 J6.2@153.502,25.014
  Bottom w0.19: J16.7@103.41,34.664 105.614,34.664 107.291,36.341 v1(107.291,38.197)
  Bottom w1: v1(133.5,46.9) v1@133.62,47.02 ; v1(153.54,22.47) v1@153.54,22.489
  Bottom w2: v1(107.733,43.849) 108.677,44.792 115.592,44.792 v1(115.988,45.188) ; v1@133.62,47.02 v1(146.515,47.02) 146.515,29.514 v1@153.54,22.489
NetC2_2: C2.2 J5.4 R1.2 | length 11.8
  Top w0.3: J5.4@3.262,42.48 5.191,42.48 5.253,42.418 v1(5.334,42.418) ; R1.2@5.225,32.775 5.258,32.808 C2.2@5.258,33.806 5.258,35.022 5.334,35.098 v1(5.334,35.179)
  Bottom w0.3: v1(5.334,35.179) v1(5.334,42.418)
NetC4_2: C4.2 D1.1 J3.5 J3.6 R23.2 | length 25.1
  Top w0.254: D1.1@29.346,59.215 29.21,59.079 29.21,57.212 C4.2@29.167,57.169 29.206,57.13 29.206,56.202 29.415,55.993 R23.2@29.415,55.391
  Top w0.3: J3.6@22.979,53.6 23.218,53.839 28.8,53.839 29.415,54.453 R23.2@29.415,55.391 ; J3.5@22.979,66.74 23.143,66.576 23.143,61.446 v1@23.2,61.389
  Bottom w0.3: J3.6@22.979,53.6 23.143,53.764 23.143,61.332 v1@23.2,61.389
  other v1: 23.215,61.395
NetC21_1: C21.1 J7.P5 SJ2.1 | length 17.7
  Top w0.2: J7.P5@16.005,11.025 v1@18.6,11.025
  Top w0.3: C21.1@17.335,21.536 17.355,21.516 18.382,21.516 ; v1@17.877,20.096 18.402,20.621 18.402,21.496 18.382,21.516 ; SJ2.1@18.732,24.169 18.732,21.866 18.382,21.516
  Bottom w0.2: v1@17.97,19.98 19.013,18.938 19.013,11.481 18.6,11.068 v1@18.6,11.025
  other v1: 18.614,11.031 17.892,20.102
NetC81_1: C81.1 J7.P6 SJ1.1 | length 16.4
  Top w0.2: J7.P6@16.005,12.375 16.011,12.381 v1(18.15,12.381)
  Top w0.3: SJ1.1@14.287,23.685 14.287,21.69 14.463,21.514 C81.1@16.005,21.514 ; C81.1@16.005,21.536 16.005,20.404 v1@16.438,19.971
  Bottom w0.2: v1@16.447,19.939 18.663,17.722 18.663,12.894 v1(18.15,12.381)
  other v1: 16.453,19.977
NetJ4_4: J4.4 R5.2 | length 7.5
  Top w0.2: J4.4@78.65,57.324 78.65,58.739 78.95,59.039 83.849,59.039 84.038,58.85 R5.2@84.038,58.384
NetJ4_21: J4.21 R14.1 | length 12.4
  Top w0.3: J4.21@74.15,53.724 74.15,52.561 75.57,51.142 v1(75.579,51.142) ; R14.1@75.625,42.389 75.75,42.264 R14.1@75.757,42.264 75.757,43.257 75.738,43.276 v1@75.738,43.195
  Bottom w0.3: v1(75.579,51.142) 75.579,51.06 75.753,50.887 75.753,43.29 v1@75.738,43.276
  other v1: 75.753,43.282
NetJ4_23: J4.23 R15.1 | length 12
  Top w0.3: J4.23@73.65,53.724 73.65,51.979 74.519,51.11 v1@74.6,51.11 ; v1@74.654,43.386 74.654,43.304 74.741,43.217 R15.1@74.741,42.264
  Bottom w0.3: v1@74.6,51.11 74.6,44.195 74.654,44.142 v1@74.654,43.386
  other v1: 74.668,43.392 74.614,51.116
NetJ4_25: J4.25 R16.1 | length 11.8
  Top w0.3: v1(73.05,52.183) 73.05,52.264 73.15,52.364 J4.25@73.15,53.724 ; R16.1@73.725,42.264 73.725,43.264 v1@73.75,43.289
  Bottom w0.3: v1(73.05,52.183) 73.05,52.176 73.577,51.649 73.577,51.437 73.75,51.264 v1@73.75,43.289
  other v1: 73.764,43.296
NetJ7_L2: J7.L2 R19.1 | length 14.6
  Top w0.328: J7.L2@32.505,7.69 35.99,7.69 37.81,9.51 R19.1@37.81,18.075
NetJ7_L3: J7.L3 R18.1 | length 5.5
  Top w0.2: J7.L3@32.505,15.71 34.948,15.71 36.71,17.472 R18.1@36.71,18.075
NetJ15_24: J15.24
NetJ15_26: J15.26
NetJ15_28: J15.28 | length 0
  Bottom w0.2: J15.28@60.226,25.467 J15.28@60.23,25.464
NetJ15_30: J15.30
NetR8_1: R8.1 USBHS.4 | length 64.3
  Top w0.2: USBHS.4@11.31,61.99 9.914,60.594 9.914,52.225 12.025,50.114 26.479,50.114 41.704,34.889 v1@44.3,34.889 ; v1(50.2,27.85) 50.277,27.773 50.277,27.531 51.157,26.65 R8.1@52.425,26.65
  Bottom w0.2: v1@44.3,34.889 44.315,34.875 44.315,33.735 v1(50.2,27.85)
  other v1: 44.315,34.895
NetR20_1: R20.1 R21.1 U1.7 | length 3
  Top w0.2: R21.1@57.069,43.248 R20.1@57.069,42.125 57.717,42.125 57.868,41.974 57.868,41.762 58.272,41.358 U1.7@58.534,41.358
ON_SD_1: SDCARD.9
PCIE.CK_1_N: J2.19 J16.19 PCIE2.3 | length 46.5
  Top w0.19: J2.19@103.65,32.264 J2.19@103.959,32.264
  Top w0.2: J2.19@103.959,32.264 103.979,32.284 104.432,32.284
  Top w0.264: 104.432,32.284 104.525,32.377 105.279,32.377 105.358,32.298 105.886,32.298 105.903,32.281 108.505,32.281 109.932,33.709 109.932,33.928 111.015,35.01 111.015,58.19 113.816,60.992 113.816,63.531 114.525,64.24 PCIE2.3@114.58,64.24
  Bottom w0.2: J16.19@103.41,32.264 104.472,32.264 104.481,32.273 104.489,32.273
  Bottom w0.264: 104.489,32.273 108.516,32.273 v1(109.912,33.669)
